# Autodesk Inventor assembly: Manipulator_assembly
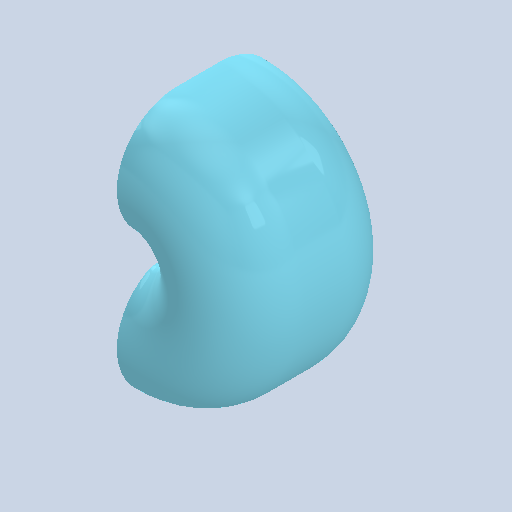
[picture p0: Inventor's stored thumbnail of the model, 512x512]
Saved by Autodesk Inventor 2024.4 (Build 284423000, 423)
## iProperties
Created: 2025-07
Part Number: Manipulator_assembly
Document SubType Name: Assembly
Designer: AdminForWorker
Title: Manipulator_assembly v4
Author: AdminForWorker
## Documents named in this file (7)
- c:\worker\convert-fusion-r03-cosv3\tmp\job-1\6\temp\files\cc6a613c-d371-4aaf-a205-cf1d6fdf3267\23da0c13-b866-41af-a883-b1e9d47e36dc.iam
- c:\worker\convert-fusion-r03-cosv3\tmp\job-1\6\temp\files\cc6a613c-d371-4aaf-a205-cf1d6fdf3267\Base v2.ipt
- c:\worker\convert-fusion-r03-cosv3\tmp\job-1\6\temp\files\cc6a613c-d371-4aaf-a205-cf1d6fdf3267\Link_1 v2.iam
- c:\worker\convert-fusion-r03-cosv3\tmp\job-1\6\temp\files\cc6a613c-d371-4aaf-a205-cf1d6fdf3267\Link_2 v2.ipt
- c:\worker\convert-fusion-r03-cosv3\tmp\job-1\6\temp\files\cc6a613c-d371-4aaf-a205-cf1d6fdf3267\Link_3 v3.ipt
- c:\worker\convert-fusion-r03-cosv3\tmp\job-1\6\temp\files\cc6a613c-d371-4aaf-a205-cf1d6fdf3267\End_effector v2.ipt
- c:\worker\convert-fusion-r03-cosv3\tmp\job-1\6\temp\files\cc6a613c-d371-4aaf-a205-cf1d6fdf3267\Workspace v3.ipt
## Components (6 placed, 6 different names)
1. Base v2:1
2. Link_1 v2:1 [sub-assembly]
3. Link_2 v2:1
4. Link_3 v3:1
5. End_effector v2:1
6. Workspace v3:1
